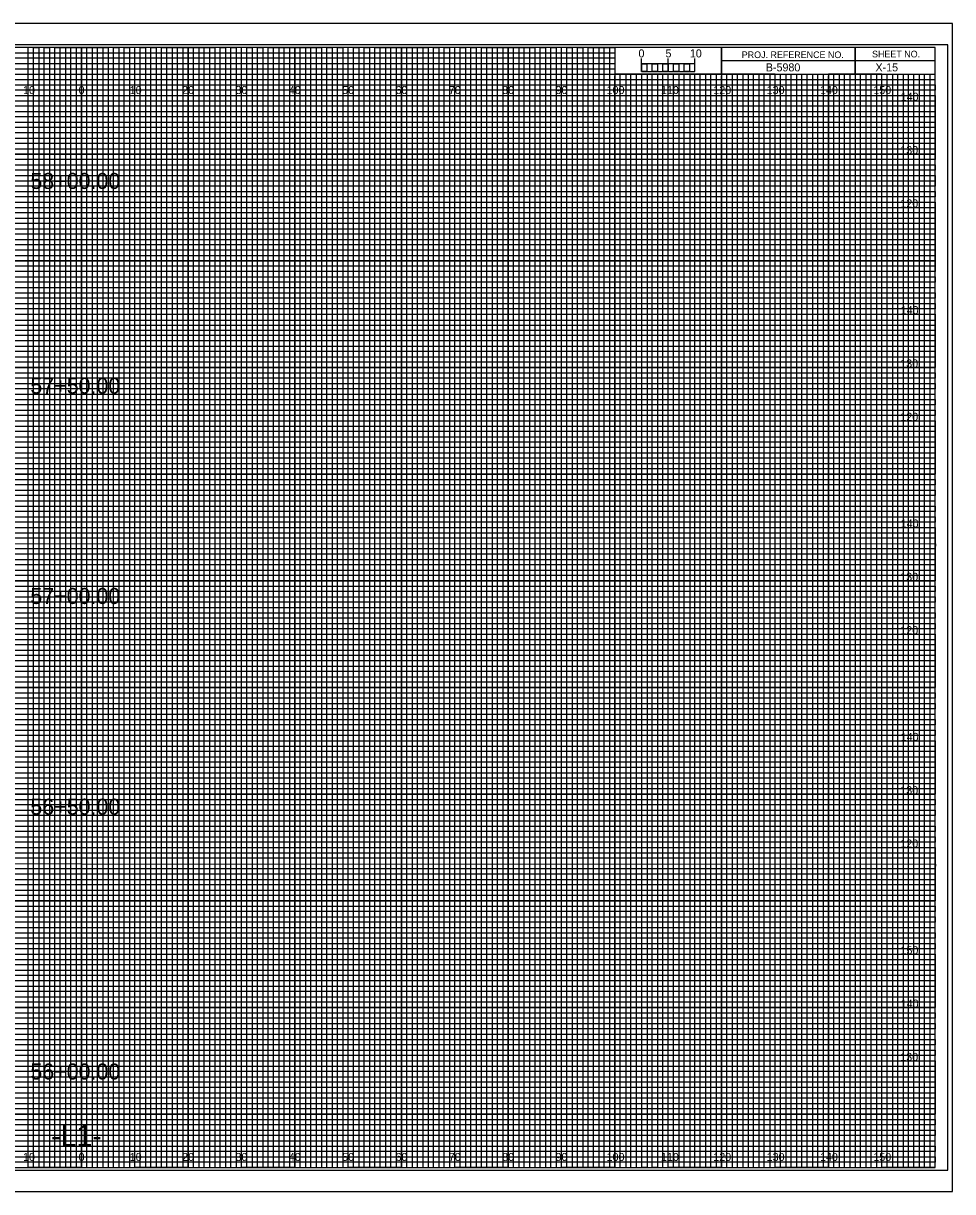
# Model space of a CAD drawing. Extents: x -13 to 323, y -5 to 3294.
# Drawn here: x 149.1 to 323.3, y 3075.5 to 3294.5 of the extents above; entities that cross this region are included whole.
import ezdxf

# ---------------------------------------------------------------- set-up
doc = ezdxf.new("R2010")
doc.units = 0
for name, color, linetype in [('Prop XS Alignment Label', 7, 'Continuous'), ('Prop XS Bar Scale Labels', 7, 'Continuous'), ('Prop XS Elevation Labels', 7, 'Continuous'), ('Prop XS Offset Labels', 7, 'Continuous'), ('Prop XS Project Number', 7, 'Continuous'), ('Prop XS Sheet Number', 7, 'Continuous'), ('Prop XS Station Labels', 7, 'Continuous'), ('Sheet Cross Section CELL', 7, 'Continuous'), ('Sheet Cross Section Grid Major CELL', 7, 'Continuous'), ('Sheet Cross Section Grid Middle CELL', 7, 'Continuous'), ('Sheet Cross Section Grid Minor 1 CELL', 7, 'Continuous'), ('Sheet Cross Section Grid Minor 2 CELL', 7, 'Continuous'), ('Sheet Cross Section Scale CELL', 7, 'Continuous'), ('Sheet Cutting Line CELL', 7, 'Continuous'), ('Sheet DOT Grid CELL', 7, 'Continuous'), ('Sheet Plot Border Inside CELL', 7, 'Continuous'), ('Sheet Plot Border Outside CELL', 7, 'Continuous')]:
    doc.layers.add(name, color=color, linetype=linetype)

msp = doc.modelspace()

# ---------------------------------------------------------------- linework, layer by layer
at = {"layer": 'Sheet Cross Section CELL'}
for p, q in [((305, 3290), (305, 3285)), ((305, 3285), (305, 3290)), ((280, 3287.5), (280, 3285)), ((320, 3287.49), (280, 3287.49)), ((280, 3285), (320, 3285))]:
    msp.add_line(p, q, dxfattribs=at)
for points in [[(320, 3290), (0, 3290), (0, 3080), (320, 3080)], [(280, 3290), (260, 3290), (260, 3285.03), (280, 3285.03)], [(320, 3290), (280, 3290), (280, 3285), (320, 3285)]]:
    msp.add_lwpolyline(points, close=True, dxfattribs=at)
at = {"layer": 'Sheet Cross Section Grid Major CELL'}
for p, q in [((150, 3290), (140, 3290)), ((150, 3080), (150, 3290)), ((170, 3290), (160, 3290)), ((160, 3290), (160, 3080)), ((170, 3080), (170, 3290)), ((190, 3290), (180, 3290)), ((180, 3290), (180, 3080)), ((190, 3080), (190, 3290)), ((210, 3290), (200, 3290)), ((200, 3290), (200, 3080)), ((210, 3080), (210, 3290)), ((230, 3290), (220, 3290)), ((220, 3290), (220, 3080)), ((230, 3080), (230, 3290)), ((250, 3290), (240, 3290)), ((240, 3290), (240, 3080)), ((250, 3080), (250, 3290)), ((260, 3290), (260, 3080)), ((270, 3080), (270, 3285)), ((290, 3285), (280, 3285)), ((280, 3285), (280, 3080)), ((290, 3080), (290, 3285)), ((310, 3285), (300, 3285)), ((300, 3285), (300, 3080)), ((310, 3080), (310, 3285)), ((160, 3080), (150, 3080)), ((180, 3080), (170, 3080)), ((200, 3080), (190, 3080)), ((220, 3080), (210, 3080)), ((240, 3080), (230, 3080)), ((260, 3080), (250, 3080)), ((280, 3080), (270, 3080)), ((300, 3080), (290, 3080)), ((320, 3080), (310, 3080)), ((320, 3080), (320, 3080))]:
    msp.add_line(p, q, dxfattribs=at)
for points in [[(0, 3280), (320, 3280), (320, 3270), (0, 3270)], [(0, 3260), (320, 3260), (320, 3250), (0, 3250)], [(0, 3240), (320, 3240), (320, 3230), (0, 3230)], [(0, 3220), (320, 3220), (320, 3210), (0, 3210)], [(0, 3200), (320, 3200), (320, 3190), (0, 3190)], [(0, 3180), (320, 3180), (320, 3170), (0, 3170)], [(0, 3160), (320, 3160), (320, 3150), (0, 3150)], [(0, 3140), (320, 3140), (320, 3130), (0, 3130)], [(0, 3120), (320, 3120), (320, 3110), (0, 3110)], [(0, 3100), (320, 3100), (320, 3090), (0, 3090)]]:
    msp.add_lwpolyline(points, dxfattribs=at)
at = {"layer": 'Sheet Cross Section Grid Middle CELL'}
for points in [[(145, 3080), (155, 3080), (155, 3290), (165, 3290), (165, 3080), (175, 3080), (175, 3290), (185, 3290), (185, 3080), (195, 3080), (195, 3290), (205, 3290), (205, 3080), (215, 3080), (215, 3290), (225, 3290), (225, 3080), (235, 3080), (235, 3290), (245, 3290), (245, 3080), (255, 3080), (255, 3290), (259.93, 3290), (260, 3290), (260, 3285), (264.99, 3285), (264.99, 3080), (275, 3080), (275, 3285), (285, 3285), (285, 3080), (295, 3080), (295, 3285), (305, 3285), (305, 3080), (315, 3080), (315, 3285)], [(0, 3285), (275, 3285)], [(0, 3265), (320, 3265), (320, 3275), (0, 3275)], [(0, 3245), (320, 3245), (320, 3255), (0, 3255)], [(0, 3225), (320, 3225), (320, 3235), (0, 3235)], [(0, 3205), (320, 3205), (320, 3215), (0, 3215)], [(0, 3185), (320, 3185), (320, 3195), (0, 3195)], [(0, 3165), (320, 3165), (320, 3175), (0, 3175)], [(0, 3145), (320, 3145), (320, 3155), (0, 3155)], [(0, 3125), (320, 3125), (320, 3135), (0, 3135)], [(0, 3105), (320, 3105), (320, 3115), (0, 3115)], [(0, 3085), (320, 3085), (320, 3095), (0, 3095)]]:
    msp.add_lwpolyline(points, dxfattribs=at)
at = {"layer": 'Sheet Cross Section Grid Minor 1 CELL'}
for p, q in [((0, 3289), (260, 3289)), ((260, 3287.98), (0, 3287.98)), ((260, 3289), (260, 3287.98)), ((0, 3287), (260, 3287)), ((260, 3285.89), (0, 3285.89)), ((260, 3287), (260, 3285.89)), ((0, 3284), (320, 3284))]:
    msp.add_line(p, q, dxfattribs=at)
for points in [[(0, 3283), (270, 3283), (320, 3283), (320, 3282), (0, 3282)], [(0, 3281), (320, 3281), (320, 3279), (0, 3279)], [(0, 3278), (320, 3278), (320, 3277), (0, 3276.98)], [(0, 3276), (320, 3276), (320, 3274), (0, 3274)], [(0, 3273), (320, 3273), (320, 3272), (0, 3272)], [(0, 3271), (320, 3271), (320, 3269), (0, 3269)], [(0, 3268), (320, 3268), (320, 3267), (0, 3267)], [(0, 3266), (320, 3266), (320, 3264), (0, 3264)], [(0, 3263), (320, 3263), (320, 3262), (0, 3262)], [(0, 3261), (320, 3261), (320, 3259), (0, 3259)], [(0, 3258), (320, 3258), (320, 3257), (0, 3257)], [(0, 3256), (320, 3256), (320, 3253.95), (320, 3253), (320, 3252), (0, 3252)], [(0, 3254), (320, 3254), (320, 3253), (0, 3253)], [(0, 3251), (320, 3251), (320, 3249), (0, 3249.03)], [(0, 3249.03), (320, 3249), (320, 3248), (0, 3248)], [(0, 3247), (320, 3247), (320, 3246), (0, 3246)], [(0, 3244), (320, 3244), (320, 3243), (0, 3243)], [(0, 3242), (320, 3242), (320, 3241), (0, 3241)], [(-0.07, 3238.89), (320, 3238.89), (320, 3237.88), (-0.07, 3237.88)], [(0, 3237), (320, 3237), (320, 3236), (0, 3236)], [(0, 3234), (320, 3234), (320, 3233), (0, 3233)], [(0, 3232), (320, 3232), (320, 3231), (0, 3231)], [(0, 3229), (320, 3229), (320, 3228), (0, 3228)], [(0, 3227), (320, 3227), (320, 3226), (0, 3226)], [(0, 3224), (320, 3224), (320, 3223), (0, 3223)], [(0, 3222), (320, 3222), (320, 3221), (0, 3221)], [(0, 3219), (320, 3219), (319.99, 3217.98), (0, 3218)], [(0, 3217), (320, 3217), (320, 3216), (0, 3216)], [(0, 3214), (320, 3214), (320, 3213), (0, 3213)], [(0, 3212), (320, 3212), (320, 3211), (0, 3211)], [(0, 3209), (320, 3209), (320, 3208), (0, 3208)], [(0, 3207), (320, 3207), (320, 3206), (0, 3206)], [(0, 3204), (320, 3204), (320, 3203), (0, 3203)], [(0, 3202), (320, 3202), (320, 3201), (0, 3201)], [(0, 3199), (320, 3199), (320, 3198), (0, 3198)], [(0, 3196.99), (320.07, 3196.91), (320, 3196), (0, 3196)], [(0, 3194), (320, 3194), (320, 3193), (0, 3193)], [(0, 3192), (320, 3192), (320, 3191), (0, 3191)], [(0, 3189), (320, 3189), (320, 3188), (0, 3188)], [(0, 3187), (320, 3187), (320, 3186), (0, 3186)], [(0, 3184), (320, 3184), (320, 3183), (0, 3183)], [(0, 3182), (320, 3182), (320, 3181), (0, 3181)], [(0, 3179), (320, 3179), (320, 3178), (0, 3178)], [(0, 3177), (320, 3177), (320, 3176), (0, 3176)], [(0, 3174), (320, 3174), (320, 3173), (0, 3173)], [(0, 3172), (320, 3172), (320, 3171), (0, 3171)], [(0, 3169), (320, 3169), (320, 3168), (0, 3168)], [(0, 3167), (320, 3167), (320, 3166), (0, 3166)], [(0, 3164), (320, 3164), (320, 3163), (0, 3163)], [(0, 3162), (320, 3162), (320, 3161), (0, 3161)], [(0, 3159), (320, 3159), (319.99, 3157.98), (0, 3158)], [(0, 3157), (320, 3157), (320, 3156), (0, 3156)], [(0, 3154), (320, 3154), (320, 3153), (0, 3153)], [(0, 3152), (320, 3152), (320, 3151), (0, 3151)], [(0, 3149), (320, 3149), (320, 3148), (0, 3148)], [(0, 3147), (320, 3147), (320, 3146), (0, 3146)], [(0, 3144), (320, 3144), (320, 3143), (0, 3143)], [(0, 3142), (320, 3142), (320, 3141), (0, 3141)], [(0, 3139), (320, 3139), (320, 3138), (0, 3138)], [(0, 3136.99), (320.07, 3136.91), (320, 3136), (0, 3136)], [(0, 3134), (320, 3134), (320, 3133), (0, 3133)], [(0, 3132), (320, 3132), (320, 3131), (0, 3131)], [(0, 3129), (320, 3129), (320, 3128), (0, 3128)], [(0, 3127), (320, 3127), (320, 3126), (0, 3126)], [(0, 3124), (320, 3124), (320, 3123), (0, 3123)], [(0, 3122), (320, 3122), (320, 3121), (0, 3121)], [(0, 3119), (320, 3119), (320, 3118), (0, 3118)], [(0, 3117), (320, 3117), (320, 3116), (0, 3116)], [(0, 3114), (320, 3114), (320, 3113), (0, 3113)], [(0, 3112), (320, 3112), (320, 3111), (0, 3111)], [(0, 3109), (320, 3109), (320, 3108), (0, 3108)], [(0, 3107), (320, 3107), (320, 3106), (0, 3106)], [(0, 3104), (320, 3104), (320, 3103), (0, 3103)], [(0, 3102), (320, 3102), (320, 3101), (0, 3101)], [(0, 3099), (320, 3099), (320, 3098), (0, 3098)], [(0, 3097), (320, 3097), (320, 3096), (0, 3096)], [(0, 3094), (320, 3094), (320, 3093), (0, 3093)], [(0, 3092), (320, 3092), (320, 3091), (0, 3091)], [(0, 3089), (320, 3089), (320, 3088), (0, 3088)], [(0, 3087), (320, 3087), (320, 3086), (0, 3086)], [(0, 3084), (320, 3084), (320, 3083), (0, 3083)], [(0, 3082), (320, 3082), (320, 3081), (0, 3081)]]:
    msp.add_lwpolyline(points, dxfattribs=at)
at = {"layer": 'Sheet Cross Section Grid Minor 2 CELL'}
for p, q in [((267, 3285), (266.01, 3285)), ((266.01, 3285), (266.01, 3080)), ((267, 3080), (267, 3285)), ((269, 3285), (268, 3285)), ((268, 3285), (268, 3080)), ((269, 3080), (269, 3285)), ((266.01, 3080), (265, 3080)), ((268, 3080), (267, 3080))]:
    msp.add_line(p, q, dxfattribs=at)
for points in [[(150, 3080), (151, 3080), (151, 3290), (152, 3290), (152, 3080)], [(152, 3080), (153, 3080), (153, 3290), (154, 3290), (154, 3080)], [(155, 3080), (156, 3080), (156, 3290), (157, 3290), (157, 3080)], [(157, 3080), (158, 3080), (158, 3290), (159, 3290), (159, 3080)], [(160, 3080), (161, 3080), (161, 3290), (162, 3290), (162, 3080)], [(162, 3080), (163, 3080), (163, 3290), (164, 3290), (164, 3080)], [(165, 3080), (166, 3080), (166, 3290), (167, 3290), (167, 3080)], [(167, 3080), (168, 3080), (168, 3290), (169, 3290), (169, 3080)], [(170, 3080), (171, 3080), (171, 3290), (172, 3290), (172, 3080)], [(172, 3080), (173, 3080), (173, 3290), (174, 3290), (174, 3080)], [(175, 3080), (176, 3080), (176, 3290), (177, 3290), (177, 3080)], [(177, 3080), (178, 3080), (178, 3290), (179, 3290), (179, 3080)], [(180, 3080), (181, 3080), (181, 3290), (182, 3290), (182, 3080)], [(182, 3080), (183, 3080), (183, 3290), (184, 3290), (184, 3080)], [(185, 3080), (186, 3080), (186, 3290), (187, 3290), (187, 3080)], [(187, 3080), (188, 3080), (188, 3290), (189, 3290), (189, 3080)], [(190, 3080), (191, 3080), (191, 3290), (192, 3290), (192, 3080)], [(192, 3080), (193, 3080), (193, 3290), (194, 3290), (194, 3080)], [(195, 3080), (196, 3080), (196, 3290), (197, 3290), (197, 3080)], [(197, 3080), (198, 3080), (198, 3290), (199, 3290), (199, 3080)], [(200, 3080), (201, 3080), (201, 3290), (202, 3290), (202, 3080)], [(202, 3080), (203, 3080), (203, 3290), (204, 3290), (204, 3080)], [(205, 3080), (206, 3080), (206, 3290), (207, 3290), (207, 3080)], [(207, 3080), (208, 3080), (208, 3290), (209, 3290), (209, 3080)], [(210, 3080), (211, 3080), (211, 3290), (212, 3290), (212, 3080)], [(212, 3080), (213, 3080), (213, 3290), (214, 3290), (214, 3080)], [(215, 3080), (216, 3080), (216, 3290), (217, 3290), (217, 3080)], [(217, 3080), (218, 3080), (218, 3290), (219, 3290), (219, 3080)], [(220, 3080), (221, 3080), (221, 3290), (222, 3290), (222, 3080)], [(222, 3080), (223, 3080), (223, 3290), (224, 3290), (224, 3080)], [(225, 3080), (226, 3080), (226, 3290), (227, 3290), (227, 3080)], [(227, 3080), (228, 3080), (228, 3290), (229, 3290), (229, 3080)], [(230, 3080), (231, 3080), (231, 3290), (232, 3290), (232, 3080)], [(232, 3080), (233, 3080), (233, 3290), (234, 3290), (234, 3080)], [(235, 3080), (236, 3080), (236, 3290), (237, 3290), (237, 3080)], [(237, 3080), (238, 3080), (238, 3290), (239, 3290), (239, 3080)], [(240, 3080), (241, 3080), (241, 3290), (242, 3290), (242, 3080)], [(242, 3080), (243, 3080), (243, 3290), (244, 3290), (244, 3080)], [(245, 3080), (246, 3080), (246, 3290), (247, 3290), (247, 3080)], [(247, 3080), (248, 3080), (248, 3290), (249, 3290), (249, 3080)], [(250, 3080), (251, 3080), (251, 3290), (252, 3290), (252, 3080)], [(252, 3080), (253, 3080), (253, 3290), (254, 3290), (254, 3080)], [(255, 3080), (256, 3080), (256, 3290), (257, 3290), (257, 3080)], [(257, 3080), (258, 3080), (258, 3290), (259, 3290), (259, 3080)], [(260, 3080), (261, 3080), (261, 3285), (262.02, 3285), (262.02, 3080)], [(262, 3080), (263, 3080), (263, 3285), (263.99, 3285), (263.99, 3080)], [(270, 3080), (270.98, 3080), (270.98, 3285), (272, 3285), (272, 3080)], [(272, 3080), (273, 3080), (273, 3285), (274.05, 3285), (274.05, 3080)], [(275, 3080), (276, 3080), (276, 3285), (277, 3285), (277, 3080)], [(277, 3080), (278, 3080), (278, 3285), (279, 3285), (279, 3080)], [(280, 3080), (281, 3080), (281, 3285), (282, 3285), (282, 3080)], [(282, 3080), (283, 3080), (283, 3285), (284, 3285), (284, 3080)], [(285, 3080), (286, 3080), (286, 3285), (287, 3285), (287, 3080)], [(287, 3080), (288, 3080), (288, 3285), (289, 3285), (289, 3080)], [(290, 3080), (291, 3080), (291, 3285), (292, 3285), (292, 3080)], [(292, 3080), (293, 3080), (293, 3285), (294, 3285), (294, 3080)], [(295, 3080), (296, 3080), (296, 3285), (297, 3285), (297, 3080)], [(297, 3080), (298, 3080), (298, 3285), (299, 3285), (299, 3080)], [(300, 3080), (301, 3080), (301, 3285), (302, 3285), (302, 3080)], [(302, 3080), (303, 3080), (303, 3285), (304, 3285), (304, 3080)], [(305, 3080), (306, 3080), (306, 3285), (307, 3285), (307, 3080)], [(307, 3080), (308, 3080), (308, 3285), (309, 3285), (309, 3080)], [(310, 3080), (311, 3080), (311, 3285), (312, 3285), (312, 3080)], [(312, 3080), (313, 3080), (313, 3285), (314, 3285), (314, 3080)], [(315, 3080), (316, 3080), (316, 3285), (317, 3285), (317, 3080)], [(317, 3080), (318, 3080), (318, 3285), (319, 3285), (319, 3080)]]:
    msp.add_lwpolyline(points, dxfattribs=at)
at = {"layer": 'Sheet Cross Section Scale CELL'}
for p, q in [((265, 3285.49), (265, 3287.9)), ((265, 3286.9), (265, 3287.9)), ((270, 3285.49), (270, 3287.9)), ((275, 3285.49), (275, 3287.9)), ((275, 3286.9), (275, 3287.9))]:
    msp.add_line(p, q, dxfattribs=at)
for points in [[(275, 3286.9), (265, 3286.9), (265, 3285.49), (275, 3285.49)], [(265, 3286.9), (266, 3286.9), (266, 3285.49), (265, 3285.49)], [(267, 3286.9), (268, 3286.9), (268, 3285.49), (267, 3285.49)], [(269, 3286.9), (270, 3286.9), (270, 3285.49), (269, 3285.49)], [(271, 3286.9), (272, 3286.9), (272, 3285.49), (271, 3285.49)], [(273, 3286.9), (274, 3286.9), (274, 3285.49), (273, 3285.49)]]:
    msp.add_lwpolyline(points, close=True, dxfattribs=at)
at = {"layer": 'Sheet Cutting Line CELL'}
for p, q in [((323.3, 3294.5), (-13.4, 3294.5)), ((-13.4, 3075.5), (323.3, 3075.5))]:
    msp.add_line(p, q, dxfattribs=at)
at = {"layer": 'Sheet DOT Grid CELL'}
for p, q in [((150, 3080), (150, 3290)), ((160, 3080), (160, 3290)), ((170, 3080), (170, 3290)), ((180, 3080), (180, 3290)), ((190, 3080), (190, 3290)), ((200, 3080), (200, 3290)), ((210, 3080), (210, 3290)), ((220, 3080), (220, 3290)), ((230, 3080), (230, 3290)), ((240, 3080), (240, 3290)), ((250, 3080), (250, 3290)), ((260, 3080), (260, 3284.69)), ((270, 3080), (270, 3284.69)), ((280, 3080), (280, 3284.69)), ((290, 3080), (290, 3284.69)), ((300, 3080), (300, 3284.69)), ((310, 3080), (310, 3284.69)), ((0, 3280), (320, 3280)), ((0, 3270), (320, 3270)), ((0, 3260), (320, 3260)), ((0, 3250), (320, 3250)), ((0, 3240), (320, 3240)), ((0, 3230), (320, 3230)), ((0, 3220), (320, 3220)), ((0, 3210), (320, 3210)), ((0, 3200), (320, 3200)), ((0, 3190), (320, 3190)), ((0, 3180), (320, 3180)), ((0, 3170), (320, 3170)), ((0, 3160), (320, 3160)), ((0, 3150), (320, 3150)), ((0, 3140), (320, 3140)), ((0, 3130), (320, 3130)), ((0, 3120), (320, 3120)), ((0, 3110), (320, 3110)), ((0, 3100), (320, 3100)), ((0, 3090), (320, 3090))]:
    msp.add_line(p, q, dxfattribs=at)
at = {"layer": 'Sheet Plot Border Inside CELL'}
msp.add_lwpolyline([(-10.8, 3079.5), (322.4, 3079.5), (322.4, 3290.5), (-10.8, 3290.5)], close=True, dxfattribs=at)
at = {"layer": 'Sheet Plot Border Outside CELL'}
msp.add_lwpolyline([(-13.4, 3075.5), (323.3, 3075.5), (323.3, 3294.5), (-13.4, 3294.5)], close=True, dxfattribs=at)

# ---------------------------------------------------------------- texts
at = {"layer": 'Prop XS Alignment Label'}
msp.add_text('-L1-', height=4, dxfattribs=at).set_placement((154.28, 3084))
at = {"layer": 'Prop XS Bar Scale Labels'}
for s, p in [('5', (269.47, 3288.12)), ('10', (274.04, 3288.12))]:
    msp.add_text(s, height=1.5, dxfattribs=at).set_placement(p)
at = {"layer": 'Prop XS Elevation Labels'}
for s, p in [('140', (313.57, 3280)), ('130', (313.49, 3270)), ('120', (313.5, 3260)), ('140', (313.57, 3240)), ('130', (313.49, 3230)), ('120', (313.5, 3220)), ('140', (313.57, 3200)), ('130', (313.49, 3190)), ('120', (313.5, 3180)), ('140', (313.57, 3160)), ('130', (313.49, 3150)), ('120', (313.5, 3140)), ('150', (313.52, 3120)), ('140', (313.57, 3110)), ('130', (313.49, 3100))]:
    msp.add_text(s, height=1.5, dxfattribs=at).set_placement(p)
at = {"layer": 'Prop XS Offset Labels'}
for s, p in [('10', (149.04, 3281.25)), ('0', (159.45, 3281.25)), ('0', (159.45, 3281.25)), ('10', (169.04, 3281.25)), ('20', (178.86, 3281.25)), ('30', (188.86, 3281.25)), ('40', (198.86, 3281.25)), ('50', (208.86, 3281.25)), ('60', (218.86, 3281.25)), ('70', (228.86, 3281.25)), ('80', (238.86, 3281.25)), ('90', (248.86, 3281.25)), ('100', (258.44, 3281.25)), ('110', (268.62, 3281.25)), ('120', (278.44, 3281.25)), ('130', (288.44, 3281.25)), ('140', (298.44, 3281.25)), ('150', (308.44, 3281.25)), ('10', (149.04, 3081.25)), ('0', (159.45, 3081.25)), ('0', (159.45, 3081.25)), ('10', (169.04, 3081.25)), ('20', (178.86, 3081.25)), ('30', (188.86, 3081.25)), ('40', (198.86, 3081.25)), ('50', (208.86, 3081.25)), ('60', (218.86, 3081.25)), ('70', (228.86, 3081.25)), ('80', (238.86, 3081.25)), ('90', (248.86, 3081.25)), ('100', (258.44, 3081.25)), ('110', (268.62, 3081.25)), ('120', (278.44, 3081.25)), ('130', (288.44, 3081.25)), ('140', (298.44, 3081.25)), ('150', (308.44, 3081.25))]:
    msp.add_text(s, height=1.5, dxfattribs=at).set_placement(p)
at = {"layer": 'Prop XS Project Number'}
msp.add_text('B-5980', height=1.5, dxfattribs=at).set_placement((288.28, 3285.5))
at = {"layer": 'Prop XS Sheet Number'}
msp.add_text('X-15', height=1.5, dxfattribs=at).set_placement((308.83, 3285.5))
at = {"layer": 'Prop XS Station Labels'}
for s, p in [('58+00.00', (150.41, 3263.46)), ('57+50.00', (150.41, 3225.08)), ('57+00.00', (150.41, 3185.66)), ('56+50.00', (150.41, 3146.16)), ('56+00.00', (150.41, 3096.52))]:
    msp.add_text(s, height=3, dxfattribs=at).set_placement(p)
at = {"layer": 'Sheet Cross Section CELL'}
for s, p in [('SHEET NO.', (308.19, 3288.12)), ('PROJ. REFERENCE NO.', (283.77, 3287.99))]:
    msp.add_text(s, height=1.25, dxfattribs=at).set_placement(p)
at = {"layer": 'Sheet Cross Section Scale CELL'}
msp.add_text('0', height=1.5, dxfattribs=at).set_placement((264.41, 3288.12))

doc.saveas('drawing.dxf')
